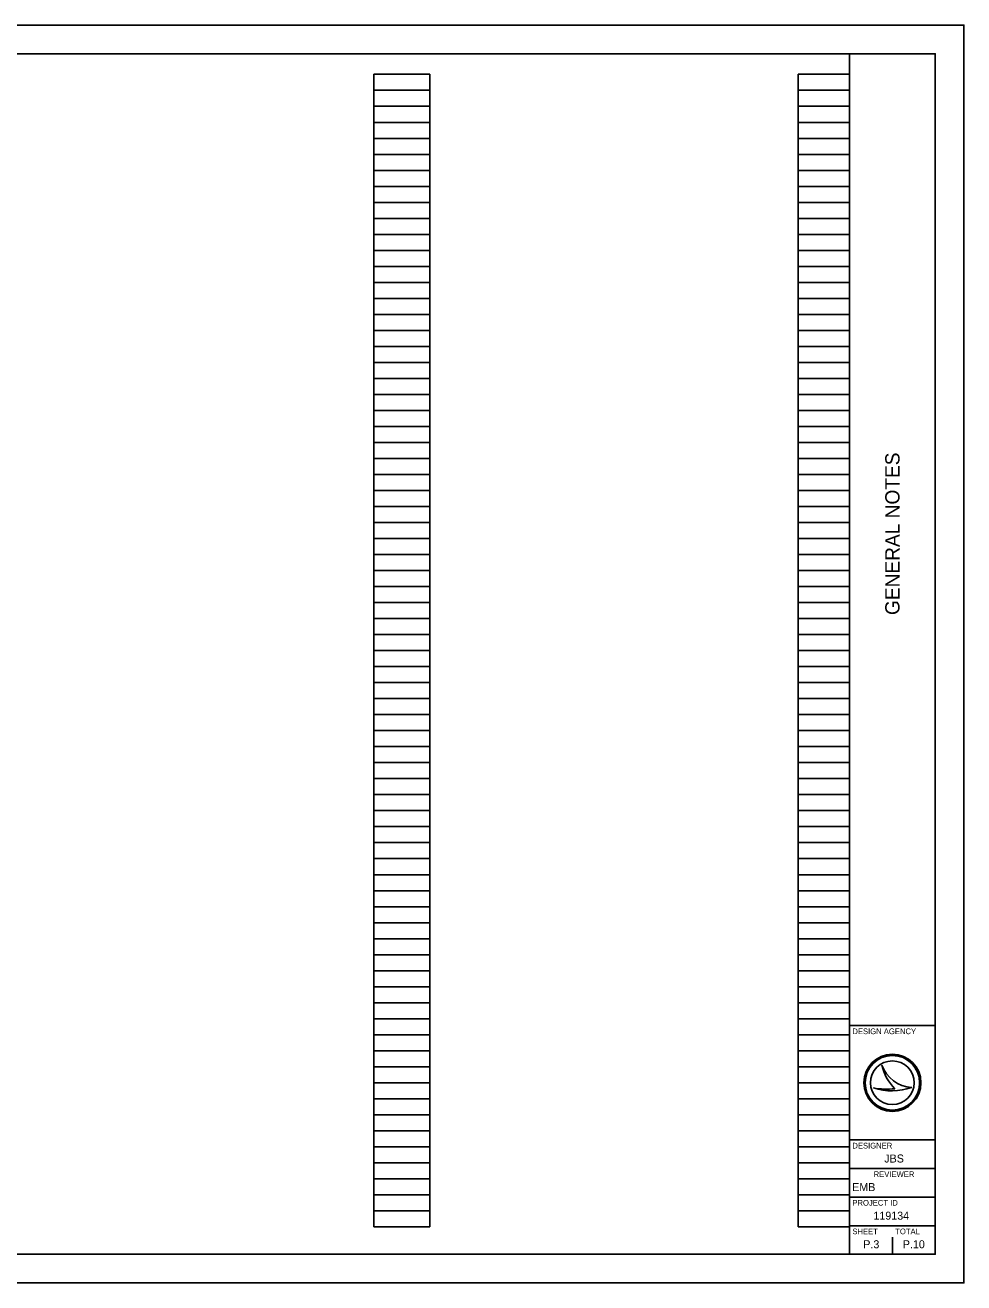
# Model space of a CAD drawing. Extents: x 0 to 34, y 0 to 22.
# Drawn here: x 17.58 to 34, y 0 to 22 of the extents above; entities that cross this region are included whole.
import ezdxf

# ---------------------------------------------------------------- set-up
doc = ezdxf.new("R2010")
doc.units = 0
for name, color, linetype in [('SH_Border', 7, 'Continuous'), ('SH_Cut_Line', 7, 'Continuous'), ('SH_Data', 7, 'Continuous')]:
    doc.layers.add(name, color=color, linetype=linetype)

msp = doc.modelspace()

# ---------------------------------------------------------------- linework, layer by layer
at = {"layer": 'SH_Border'}
for p, q in [((32, 0.5), (32, 21.5)), ((32, 4.5), (33.5, 4.5)), ((32, 2.5), (33.5, 2.5)), ((32, 2), (33.5, 2)), ((32, 1.5), (33.5, 1.5)), ((32, 1), (33.5, 1))]:
    msp.add_line(p, q, dxfattribs=at)
msp.add_lwpolyline([(1.5, 21.5), (33.5, 21.5), (33.5, 0.5), (1.5, 0.5)], close=True, dxfattribs=at)
at = {"layer": 'SH_Cut_Line'}
msp.add_lwpolyline([(0, 0), (34, 0), (34, 22), (0, 22)], close=True, dxfattribs=at)
at = {"layer": 'SH_Data'}
for p, q in [((23.68, 0.98), (23.68, 21.14)), ((23.68, 21.14), (24.66, 21.14)), ((24.66, 0.98), (24.66, 21.14)), ((31.1, 0.98), (31.1, 21.14)), ((31.1, 21.14), (32, 21.14)), ((32, 0.98), (32, 21.14)), ((23.68, 20.86), (24.66, 20.86)), ((31.1, 20.86), (32, 20.86)), ((23.68, 20.58), (24.66, 20.58)), ((31.1, 20.58), (32, 20.58)), ((23.68, 20.3), (24.66, 20.3)), ((31.1, 20.3), (32, 20.3)), ((23.68, 20.02), (24.66, 20.02)), ((31.1, 20.02), (32, 20.02)), ((23.68, 19.74), (24.66, 19.74)), ((31.1, 19.74), (32, 19.74)), ((23.68, 19.46), (24.66, 19.46)), ((31.1, 19.46), (32, 19.46)), ((23.68, 19.18), (24.66, 19.18)), ((31.1, 19.18), (32, 19.18)), ((23.68, 18.9), (24.66, 18.9)), ((31.1, 18.9), (32, 18.9)), ((23.68, 18.62), (24.66, 18.62)), ((31.1, 18.62), (32, 18.62)), ((23.68, 18.34), (24.66, 18.34)), ((31.1, 18.34), (32, 18.34)), ((23.68, 18.06), (24.66, 18.06)), ((31.1, 18.06), (32, 18.06)), ((23.68, 17.78), (24.66, 17.78)), ((31.1, 17.78), (32, 17.78)), ((23.68, 17.5), (24.66, 17.5)), ((31.1, 17.5), (32, 17.5)), ((23.68, 17.22), (24.66, 17.22)), ((31.1, 17.22), (32, 17.22)), ((23.68, 16.94), (24.66, 16.94)), ((31.1, 16.94), (32, 16.94)), ((23.68, 16.66), (24.66, 16.66)), ((31.1, 16.66), (32, 16.66)), ((23.68, 16.38), (24.66, 16.38)), ((31.1, 16.38), (32, 16.38)), ((23.68, 16.1), (24.66, 16.1)), ((31.1, 16.1), (32, 16.1)), ((23.68, 15.82), (24.66, 15.82)), ((31.1, 15.82), (32, 15.82)), ((23.68, 15.54), (24.66, 15.54)), ((31.1, 15.54), (32, 15.54)), ((23.68, 15.26), (24.66, 15.26)), ((31.1, 15.26), (32, 15.26)), ((23.68, 14.98), (24.66, 14.98)), ((31.1, 14.98), (32, 14.98)), ((23.68, 14.7), (24.66, 14.7)), ((31.1, 14.7), (32, 14.7)), ((23.68, 14.42), (24.66, 14.42)), ((31.1, 14.42), (32, 14.42)), ((23.68, 14.14), (24.66, 14.14)), ((31.1, 14.14), (32, 14.14)), ((23.68, 13.86), (24.66, 13.86)), ((31.1, 13.86), (32, 13.86)), ((23.68, 13.58), (24.66, 13.58)), ((31.1, 13.58), (32, 13.58)), ((23.68, 13.3), (24.66, 13.3)), ((31.1, 13.3), (32, 13.3)), ((23.68, 13.02), (24.66, 13.02)), ((31.1, 13.02), (32, 13.02)), ((23.68, 12.74), (24.66, 12.74)), ((31.1, 12.74), (32, 12.74)), ((23.68, 12.46), (24.66, 12.46)), ((31.1, 12.46), (32, 12.46)), ((23.68, 12.18), (24.66, 12.18)), ((31.1, 12.18), (32, 12.18)), ((23.68, 11.9), (24.66, 11.9)), ((31.1, 11.9), (32, 11.9)), ((23.68, 11.62), (24.66, 11.62)), ((31.1, 11.62), (32, 11.62)), ((23.68, 11.34), (24.66, 11.34)), ((31.1, 11.34), (32, 11.34)), ((23.68, 11.06), (24.66, 11.06)), ((31.1, 11.06), (32, 11.06)), ((23.68, 10.78), (24.66, 10.78)), ((31.1, 10.78), (32, 10.78)), ((23.68, 10.5), (24.66, 10.5)), ((31.1, 10.5), (32, 10.5)), ((23.68, 10.22), (24.66, 10.22)), ((31.1, 10.22), (32, 10.22)), ((23.68, 9.94), (24.66, 9.94)), ((31.1, 9.94), (32, 9.94)), ((23.68, 9.66), (24.66, 9.66)), ((31.1, 9.66), (32, 9.66)), ((23.68, 9.38), (24.66, 9.38)), ((31.1, 9.38), (32, 9.38)), ((23.68, 9.1), (24.66, 9.1)), ((31.1, 9.1), (32, 9.1)), ((23.68, 8.82), (24.66, 8.82)), ((31.1, 8.82), (32, 8.82)), ((23.68, 8.54), (24.66, 8.54)), ((31.1, 8.54), (32, 8.54)), ((23.68, 8.26), (24.66, 8.26)), ((31.1, 8.26), (32, 8.26)), ((23.68, 7.98), (24.66, 7.98)), ((31.1, 7.98), (32, 7.98)), ((23.68, 7.7), (24.66, 7.7)), ((31.1, 7.7), (32, 7.7)), ((23.68, 7.42), (24.66, 7.42)), ((31.1, 7.42), (32, 7.42)), ((23.68, 7.14), (24.66, 7.14)), ((31.1, 7.14), (32, 7.14)), ((23.68, 6.86), (24.66, 6.86)), ((31.1, 6.86), (32, 6.86)), ((23.68, 6.58), (24.66, 6.58)), ((31.1, 6.58), (32, 6.58)), ((23.68, 6.3), (24.66, 6.3)), ((31.1, 6.3), (32, 6.3)), ((23.68, 6.02), (24.66, 6.02)), ((31.1, 6.02), (32, 6.02)), ((23.68, 5.74), (24.66, 5.74)), ((31.1, 5.74), (32, 5.74)), ((23.68, 5.46), (24.66, 5.46)), ((31.1, 5.46), (32, 5.46)), ((23.68, 5.18), (24.66, 5.18)), ((31.1, 5.18), (32, 5.18)), ((23.68, 4.9), (24.66, 4.9)), ((31.1, 4.9), (32, 4.9)), ((23.68, 4.62), (24.66, 4.62)), ((31.1, 4.62), (32, 4.62)), ((23.68, 4.34), (24.66, 4.34)), ((31.1, 4.34), (32, 4.34)), ((23.68, 4.06), (24.66, 4.06)), ((31.1, 4.06), (32, 4.06)), ((23.68, 3.78), (24.66, 3.78)), ((31.1, 3.78), (32, 3.78)), ((32.567, 3.81), (32.567, 3.81)), ((23.68, 3.5), (24.66, 3.5)), ((31.1, 3.5), (32, 3.5)), ((32.417, 3.41), (32.417, 3.41)), ((32.75, 3.5), (32.75, 3.5)), ((33.087, 3.419), (33.087, 3.419)), ((23.68, 3.22), (24.66, 3.22)), ((31.1, 3.22), (32, 3.22)), ((23.68, 2.94), (24.66, 2.94)), ((31.1, 2.94), (32, 2.94)), ((23.68, 2.66), (24.66, 2.66)), ((31.1, 2.66), (32, 2.66)), ((23.68, 2.38), (24.66, 2.38)), ((31.1, 2.38), (32, 2.38)), ((23.68, 2.1), (24.66, 2.1)), ((31.1, 2.1), (32, 2.1)), ((23.68, 1.82), (24.66, 1.82)), ((31.1, 1.82), (32, 1.82)), ((23.68, 1.54), (24.66, 1.54)), ((31.1, 1.54), (32, 1.54)), ((23.68, 1.26), (24.66, 1.26)), ((31.1, 1.26), (32, 1.26)), ((23.68, 0.98), (24.66, 0.98)), ((31.1, 0.98), (32, 0.98)), ((32.375, 0.675), (32.375, 0.675)), ((32.75, 0.5), (32.75, 0.8))]:
    msp.add_line(p, q, dxfattribs=at)
for radius in [0.5, 0.477, 0.477, 0.382]:
    msp.add_circle((32.75, 3.5), radius, dxfattribs=at)
for centre, radius, start, end in [((33.116, 3.998), 0.58, 198.9257, 198.9319), ((33.347, 3.97), 0.796, 191.6379, 191.6421), ((33.116, 3.998), 0.58, 198.9319, 267.1657), ((33.347, 3.97), 0.796, 191.6421, 226.0947), ((32.739, 4.37), 1.013, 251.4576, 290.0832), ((32.648, 4.654), 1.266, 259.4964, 259.4995), ((32.739, 4.37), 1.013, 251.4527, 251.4576), ((32.648, 4.654), 1.266, 259.4995, 276.6672)]:
    msp.add_arc(centre, radius, start, end, dxfattribs=at)

# ---------------------------------------------------------------- texts
msp.add_text('GENERAL NOTES', height=0.25, rotation=90, dxfattribs=at).set_placement((32.875, 11.682))
for s, height, p in [('DESIGN AGENCY', 0.1, (32.05, 4.35)), ('DESIGNER', 0.1, (32.05, 2.35)), ('JBS', 0.14, (32.608, 2.105)), ('REVIEWER', 0.1, (32.422, 1.85)), ('EMB', 0.14, (32.047, 1.605)), ('PROJECT ID', 0.1, (32.05, 1.35)), ('119134', 0.14, (32.418, 1.105)), ('SHEET', 0.1, (32.05, 0.85)), ('TOTAL', 0.1, (32.8, 0.85)), ('P.3', 0.14, (32.241, 0.605)), ('P.10', 0.14, (32.932, 0.605))]:
    msp.add_text(s, height=height, dxfattribs=at).set_placement(p)

doc.saveas('drawing.dxf')
